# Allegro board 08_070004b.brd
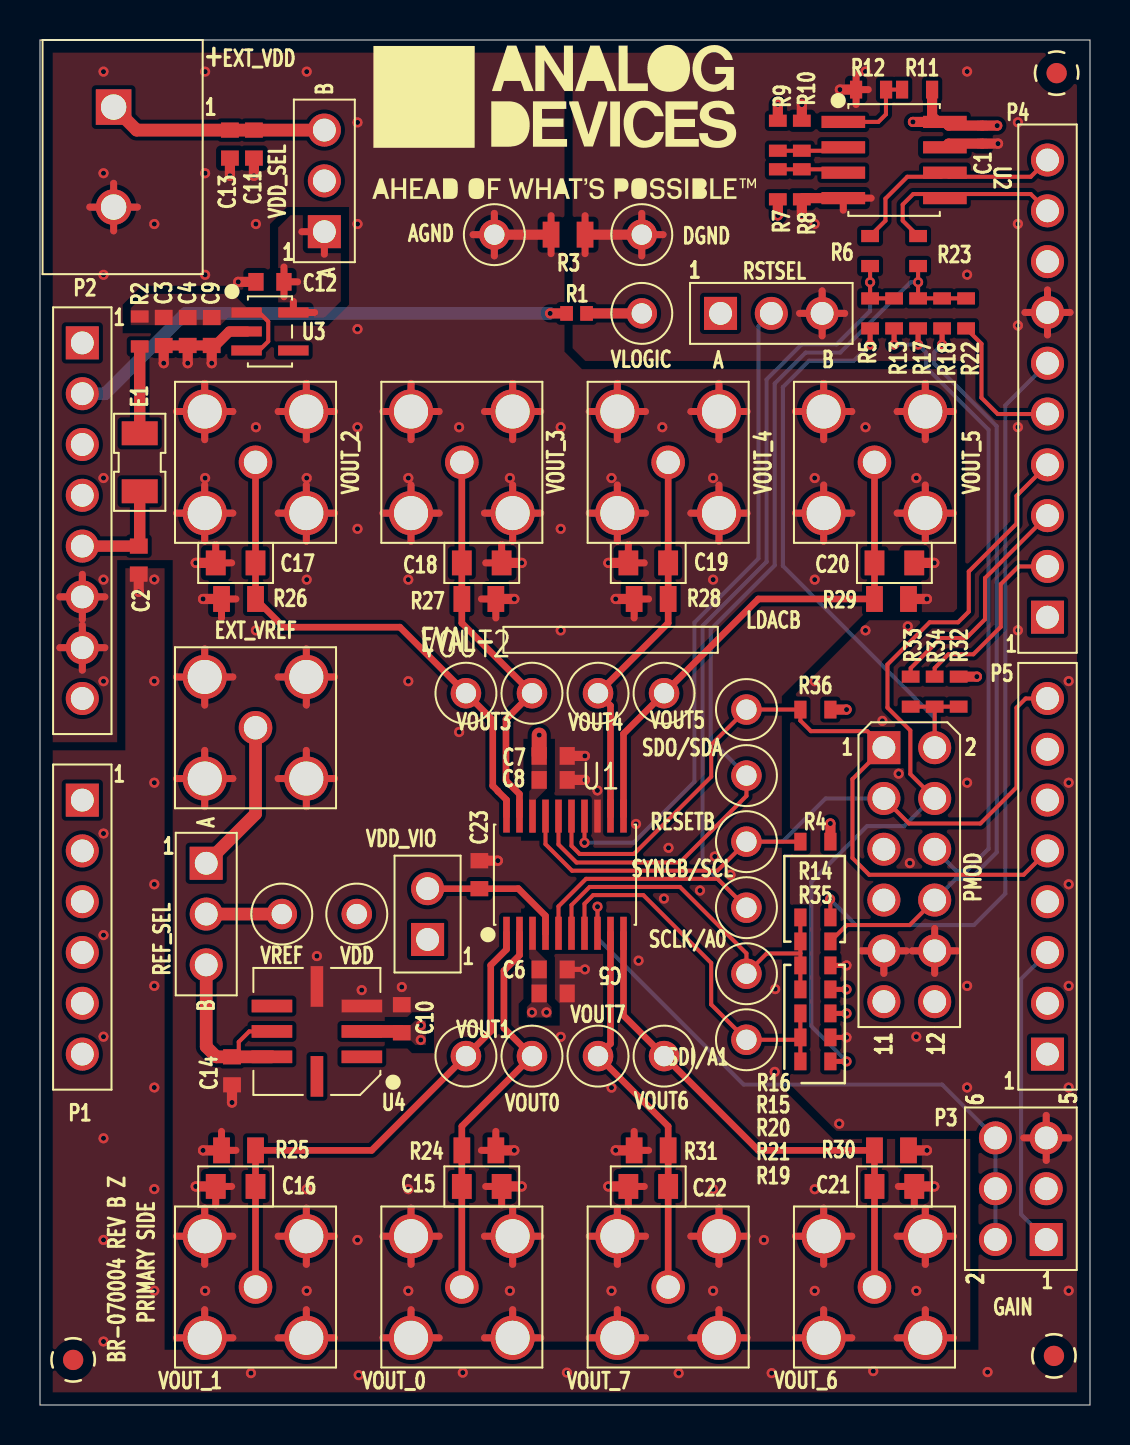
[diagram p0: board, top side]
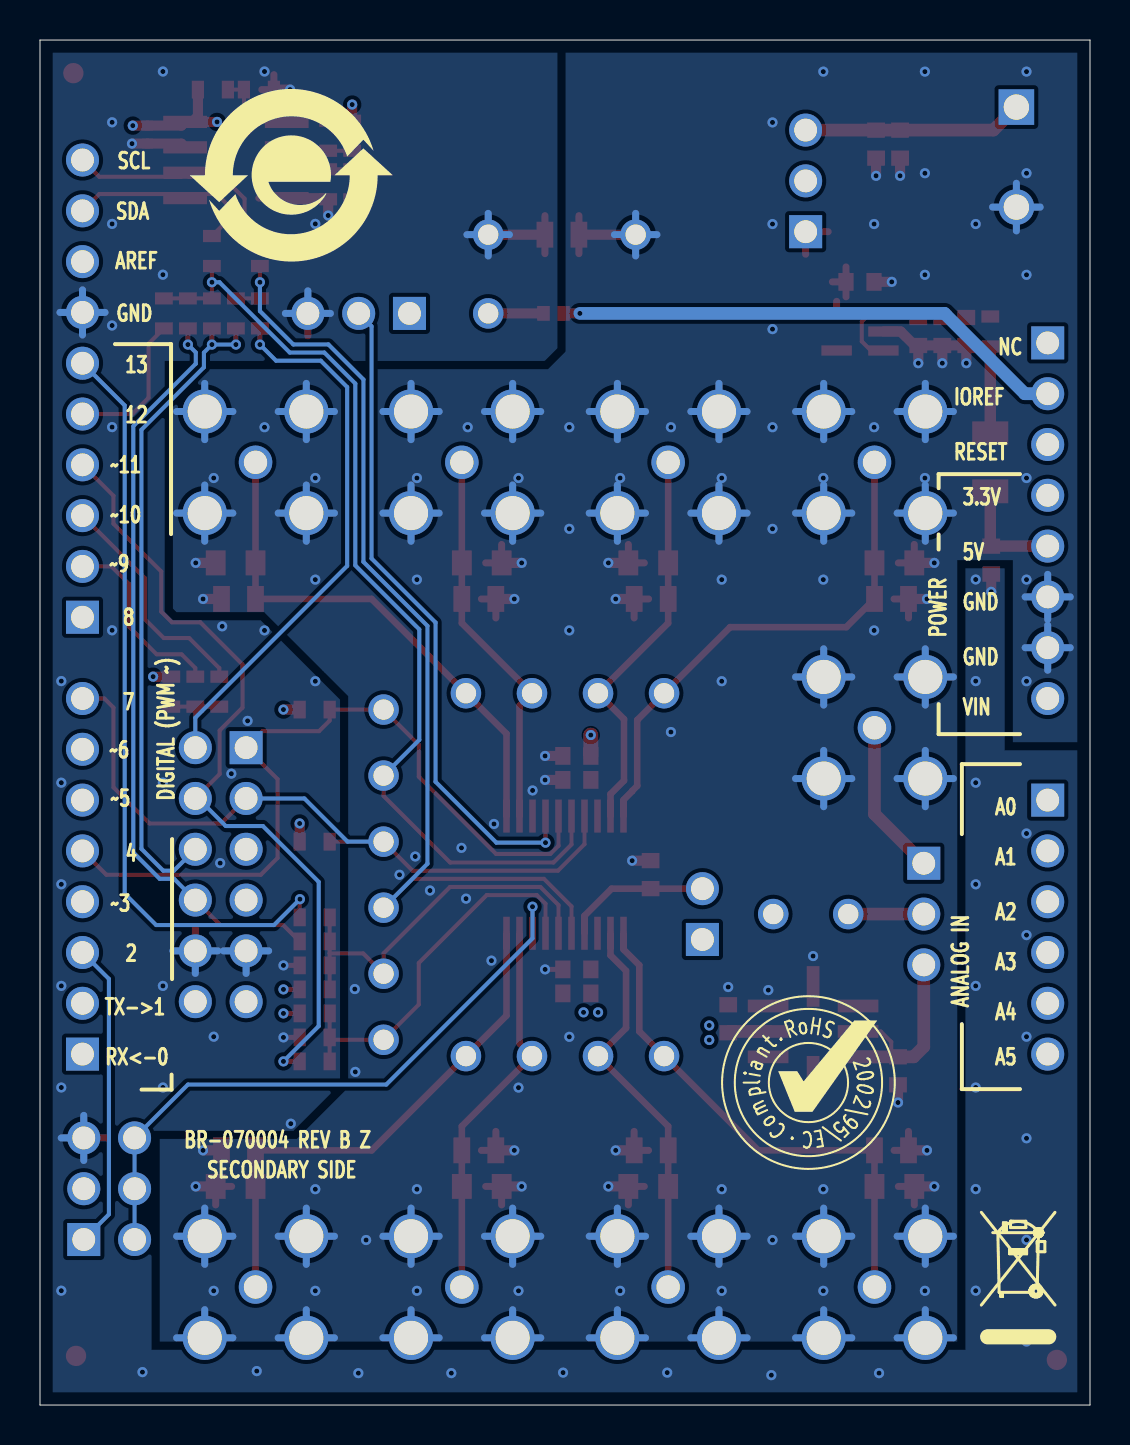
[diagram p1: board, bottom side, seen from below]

Outline 52.5 x 68.25 mm; copper layers: TOP, L2_GND, L3_PWR, BOTTOM. Coordinates in mm from the lower left corner of the outline.
Outline path: 0,68.25 52.5,68.25 52.5,0 0,0 0,68.25

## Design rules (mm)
constraint set DEFAULT: min track width 0.203
net group VOUT: nets DAC_OUT0 DAC_OUT1 DAC_OUT2 DAC_OUT3 DAC_OUT4 DAC_OUT5 DAC_OUT6 DAC_OUT7

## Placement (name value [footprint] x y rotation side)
AGND  BLK  [CNKEY5001TP]  22.72 58.52 90 top
C1  0.1uF  [C0402]  47.12 63.52 90 top
C2  10uF  [C0603]  4.94 42.25 270 top
C3  4.7UF  [C0603]  6.19 53.68 270 top
C4  0.1uF  [C0603]  7.39 53.68 270 top
C5  10uF  [C0603]  25.66 20.58 180 top
C6  0.1uF  [C0603]  25.66 21.78 0 top
C7  0.1uF  [C0603]  25.66 32.45 0 top
C8  0.1uF  [C0603]  25.66 31.25 0 top
C9  1uF  [C0603]  8.59 53.68 270 top
C10  0.1uF  [C0603]  18.09 19.31 90 top
C11  0.1uF  [C0603]  10.7 63.05 270 top
C12  1uF  [C0603]  11.5 56.16 180 top
C13  10uF  [C0603]  9.5 63.05 270 top
C14  1uF  [C0603]  9.6 16.71 270 top
C15  10NF  [C0805-2]  22.09 10.93 0 top
C16  10NF  [C0805-2]  9.78 10.93 180 top
C17  10NF  [C0805-2]  9.78 42.1 180 top
C18  10NF  [C0805-2]  22.09 42.1 0 top
C19  10NF  [C0805-2]  30.41 42.1 180 top
C20  10NF  [C0805-2]  42.72 42.1 0 top
C21  10NF  [C0805-2]  42.72 10.93 0 top
C22  10NF  [C0805-2]  30.41 10.93 180 top
C23  0.1uF  [C0603]  21.97 26.52 270 top
DGND  BLK  [CNKEY5001TP]  30.09 58.52 90 top
E1  600OHM  [L1206H71]  4.99 47.13 90 top
EXT_VDD  691102710002  [CNWURTH691102710002]  3.68 64.9 270 top
EXT_VREF  131-3701-261  [CNJOHNSON131-3701-261]  10.78 33.86 90 top
LDACB  WHT  [CNKEY5001TP]  35.32 34.77 0 top
NOREF  -  []  26.42 80.36 0 top
NOREF#2  -  []  96.35 33.6 0 top
NOREF#3  -  []  -60.3 -65 0 top
NOREF#4  -  [unnamed#2]  50.83 66.59 0 top
NOREF#5  -  []  0.46 344.29 0 top
NOREF#6  -  []  0 68.25 270 top
NOREF#7  -  [unnamed#2]  1.66 2.25 0 top
NOREF#8  -  []  48.67 371.65 0 top
NOREF#9  -  []  26.23 64.13 0 top
NOREF#10  -  []  52.5 0 90 top
NOREF#11  -  []  0 0 0 top
NOREF#12  -  []  52.5 0 90 top
NOREF#13  -  []  52.5 68.25 180 top
NOREF#14  -  []  0 68.25 0 top
NOREF#15  -  []  0 68.25 0 top
NOREF#16  -  []  0 0 0 top
NOREF#17  -  [unnamed#2]  50.7 2.45 0 top
NOREF#18  -  []  -49.91 -63.27 0 top
NOREF#19  -  []  2.12 17.55 0 top
NOREF#20  -  []  2.12 53.11 270 top
NOREF#21  -  []  0 0 0 top
NOREF#22  -  []  52.5 0 0 top
NOREF#23  -  []  2.12 17.55 0 top
NOREF#24  -  []  81.92 108.01 0 top
NOREF#25  -  []  39.94 61.49 180 bottom
NOREF#26  -  []  3.79 3.09 180 bottom
NOREF#27  -  []  14.08 16.12 180 bottom
P1  SSQ-106-03-G-S  [CNSAMTECSSQ-106-XX-X-S]  2.12 30.25 270 top
P2  SSQ-108-03-G-S  [CNSAMTECSSQ-108-XX-X-S]  2.12 53.11 270 top
P3  TSW-103-08-G-D  [CNSAMTEC2X3H330LD36]  50.31 8.27 90 top
P4  SSQ-110-03-G-S  [CNSAMTECSSQ-110-XX-X-S]  50.38 39.39 90 top
P5  SSQ-108-03-G-S  [CNSAMTECSSQ-108-XX-X-S]  50.38 17.55 90 top
PMOD  TSW-106-08-G-D  [CNBERG2X6H330LD36]  42.19 32.87 270 top
R1  0  [R0402]  26.83 54.58 0 top
R2  1.6  [R0603]  4.99 53.68 90 top
R3  0  [R0805]  26.4 58.52 180 top
R4  100K  [R0603]  38.77 28.17 180 top
R5  0  [R0603]  41.5 54.58 90 top
R6  0  [R0603]  41.5 57.7 270 top
R7  0  [R0603]  36.89 61.04 90 top
R8  100K  [R0603]  38.09 61.04 270 top
R9  100K  [R0603]  36.89 63.46 270 top
R10  0  [R0603]  38.09 63.46 90 top
R11  0  [R0603]  43.85 65.77 180 top
R12  100K  [R0603]  41.55 65.77 180 top
R13  0  [R0603]  42.7 54.58 90 top
R14  0  [R0603]  38.77 24.38 180 top
R15  0  [R0603]  38.77 20.78 180 top
R16  0  [R0603]  38.77 21.98 180 top
R17  0  [R0603]  43.9 54.58 90 top
R18  0  [R0603]  45.1 54.58 90 top
R19  0  [R0603]  38.77 17.18 180 top
R20  0  [R0603]  38.77 19.58 180 top
R21  0  [R0603]  38.77 18.38 180 top
R22  0  [R0603]  46.3 54.58 90 top
R23  0  [R0603]  43.9 57.7 270 top
R24  1K  [R0805]  21.94 12.73 0 top
R25  1K  [R0805]  9.93 12.73 180 top
R26  1K  [R0805]  9.93 40.3 180 top
R27  1K  [R0805]  21.94 40.3 0 top
R28  1K  [R0805]  30.56 40.3 180 top
R29  1K  [R0805]  42.57 40.3 0 top
R30  1K  [R0805]  42.57 12.73 0 top
R31  1K  [R0805]  30.56 12.73 180 top
R32  100K  [R0603]  45.93 35.67 90 top
R33  0  [R0603]  43.53 35.67 90 top
R34  0  [R0603]  44.73 35.67 90 top
R35  0  [R0603]  38.77 23.18 180 top
R36  100K  [R0603]  38.77 34.77 180 top
REF_SEL  YMC03SAAN  [CNTHMHDR1X3L300W100H343_A]  8.31 27.09 270 top
RESETB  WHT  [CNKEY5001TP]  35.32 28.17 0 top
RSTSEL  YMC03SAAN  [CNTHMHDR1X3L300W100H343_A]  34.03 54.58 0 top
SCLK/A0  WHT  [CNKEY5001TP]  35.32 21.56 0 top
SDI/A1  WHT  [CNKEY5001TP]  35.32 18.26 0 top
SDO/SDA  WHT  [CNKEY5001TP]  35.32 31.47 0 top
SYNCB/SCL  WHT  [CNKEY5001TP]  35.32 24.87 0 top
U1  AD5676RBRUZ  [TSSOP20]  26.25 26.52 0 top
U2  24AA32A-I/SN  [SO8]  42.7 62.25 270 top
U3  ADP121-AUJZ33  [TSOT-5]  11.5 53.68 270 top
U4  ADR4525DEZ  [LCC8]  13.85 18.68 90 top
VDD  RED  [CNKEY5001TP]  15.84 24.55 0 top
VDD_SEL  YMC03SAAN  [CNTHMHDR1X3L300W100H343_A]  14.22 58.67 90 top
VDD_VIO  M20-9990246  [CNHARWIN-M20-9990246]  19.38 23.28 90 top
VLOGIC  RED  [CNKEY5001TP]  30.09 54.58 0 top
VOUT0  RED  [CNKEY5001TP]  24.6 17.44 0 top
VOUT1  RED  [CNKEY5001TP]  21.3 17.44 0 top
VOUT2  RED  [CNKEY5001TP]  21.3 35.59 0 top
VOUT3  RED  [CNKEY5001TP]  24.6 35.59 0 top
VOUT4  RED  [CNKEY5001TP]  27.9 35.59 0 top
VOUT5  RED  [CNKEY5001TP]  31.2 35.59 0 top
VOUT6  RED  [CNKEY5001TP]  31.2 17.44 0 top
VOUT7  RED  [CNKEY5001TP]  27.9 17.44 0 top
VOUT_0  131-3701-261  [CNJOHNSON131-3701-261]  21.09 5.9 90 top
VOUT_1  131-3701-261  [CNJOHNSON131-3701-261]  10.78 5.9 90 top
VOUT_2  131-3701-261  [CNJOHNSON131-3701-261]  10.78 47.13 90 top
VOUT_3  131-3701-261  [CNJOHNSON131-3701-261]  21.09 47.13 90 top
VOUT_4  131-3701-261  [CNJOHNSON131-3701-261]  31.41 47.13 90 top
VOUT_5  131-3701-261  [CNJOHNSON131-3701-261]  41.72 47.13 90 top
VOUT_6  131-3701-261  [CNJOHNSON131-3701-261]  41.72 5.9 90 top
VOUT_7  131-3701-261  [CNJOHNSON131-3701-261]  31.41 5.9 90 top
VREF  RED  [CNKEY5001TP]  12.09 24.55 0 top

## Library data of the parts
AGND DGND = CNTP1P: Tolerance: N/A; User Part Number: UPN; alternate symbols: (CNKEY5001TP); part number: CNTP1P_TH-BLK,E005347,CNKEY5001TP; tolerance: N/A
C1 = CAP: User Part Number: UPN; Tolerance: 10; alternate symbols: (C0402L); part number: CAP_SM-0.1UF,16V,10,E028141,C0402; tolerance: 10
C2 = CAP: User Part Number: UPN; Tolerance: 20; alternate symbols: (C0603L); part number: CAP_SM-10UF,6.3V,20,E007143,C0603; tolerance: 20
C3 = CAP: User Part Number: UPN; Tolerance: 20; alternate symbols: (C0603L); part number: CAP_SM-4.7UF,10V,20,E054276,C0603; tolerance: 20
C4 C10 = CAP: User Part Number: UPN; Tolerance: 10; alternate symbols: (C0603L); part number: CAP_SM-0.1UF,50V,10,E031401,C0603; tolerance: 10
C5 C13 = CAP: User Part Number: UPN; Tolerance: 20; alternate symbols: (C0603L); part number: CAP_SM-10UF,10V,20,E022682,C0603; tolerance: 20
C6-C8 C11 C23 = CAP: User Part Number: UPN; Tolerance: 10; alternate symbols: (C0603L); part number: CAP_SM-0.1UF,16V,10,E015036,C0603; tolerance: 10
C9 C12 C14 = CAP: User Part Number: UPN; Tolerance: 10; alternate symbols: (C0603L); part number: CAP_SM-1UF,16V,10,E020111,C0603; tolerance: 10
C15-C22 = CAP: Tolerance: 10; User Part Number: UPN; alternate symbols: (C0805-2); part number: CAP_SM-10NF,200V,10,E042770,C0805-2; tolerance: 10
E1 = FERRITE: User Part Number: UPN; Tolerance: 25; alternate symbols: (L1206H71); part number: FERRITE_SM-600OHM,25,E048457,L1206H71; tolerance: 25
EXT_VDD = CN2P: Tolerance: N/A; User Part Number: UPN; alternate symbols: (CNWURTH691102710002); part number: CN2P_TH-691102710002,E048111,CNWURTH691102710002; tolerance: N/A
EXT_VREF VOUT_0-VOUT_7 = CNBNC5P: Tolerance: N/A; User Part Number: UPN; alternate symbols: (CNJOHNSON131-3701-261); part number: CNBNC5P_TH-131-3701-261,E012123,CNJOHNSON131-3701-261; tolerance: N/A
LDACB RESETB SCLK/A0 SDI/A1 SDO/SDA SYNCB/SCL = CNTP1P: Tolerance: N/A; User Part Number: UPN; alternate symbols: (CNKEY5001TP); part number: CNTP1P_TH-WHT,E006153,CNKEY5001TP; tolerance: N/A
P1 = CN6P: User Part Number: UPN; Tolerance: N/A; alternate symbols: (CNSAMTECSSQ-106-XX-X-S); part number: CN6P_TH-SSQ-106-03-G-S,E020477,CNSAMTECSSQ-106-XX-X-S; tolerance: N/A
P2 P5 = CN8P_A: User Part Number: UPN; Tolerance: N/A; alternate symbols: (CNSAMTECSSQ-108-XX-X-S); part number: CN8P_A_TH-SSQ-108-03-G-S,E020478,CNSAMTECSSQ-108-XX-X-S; tolerance: N/A
P3 = CN6P_ODD_EVEN: Tolerance: N/A; User Part Number: UPN; alternate symbols: (CNSAMTEC2X3H330LD36); part number: CN6P_ODD_EVEN_TH-TSW-103-08-G-D,E006383,CNSAMTEC2X3H330LD36; tolerance: N/A
P4 = CN10P: User Part Number: UPN; Tolerance: N/A; alternate symbols: (CNSAMTECSSQ-110-XX-X-S); part number: CN10P_TH-SSQ-110-03-G-S,E020479,CNSAMTECSSQ-110-XX-X-S; tolerance: N/A
PMOD = CN12P: Tolerance: N/A; User Part Number: UPN; alternate symbols: (CNBERG2X6H330LD36); part number: CN12P_TH-TSW-106-08-G-D,E000735,CNBERG2X6H330LD36; tolerance: N/A
R1 = RES: User Part Number: UPN; Tolerance: JUMPER; alternate symbols: (R0402); part number: RES_SM-0,E025232,1/16W,JUMPER,R0402; tolerance: JUMPER
R2 = RES: User Part Number: UPN; Tolerance: 1; alternate symbols: (R0603L); part number: RES_SM-1.6,E022192,1/5W,1,R0603; tolerance: 1
R3 = RES: User Part Number: UPN; Tolerance: JUMPER; alternate symbols: (R0805L); part number: RES_SM-0,E055446,1/2W,JUMPER,R0805; tolerance: JUMPER
R4 R36 = RES: User Part Number: UPN; Tolerance: 1; alternate symbols: (R0603L); part number: RES_SM-100K,E017869,1/10W,1,R0603; tolerance: 1
R5 R6 R13-R23 R33-R35 = RES: User Part Number: UPN; Tolerance: JUMPER; alternate symbols: (R0603L); part number: RES_SM-0,E034483,1/10W,JUMPER,R0603; tolerance: JUMPER
R7 R10 R11 = RES: User Part Number: UPN; Tolerance: JUMPER; alternate symbols: (R0603L); part number: RES_SM-0,E007502,1/10W,JUMPER,R0603; tolerance: JUMPER
R8 R9 R12 = RES: User Part Number: UPN; Tolerance: 1; alternate symbols: (R0603L); part number: RES_SM-100K,E018430,1/16W,1,R0603; tolerance: 1
R24-R31 = RES: User Part Number: UPN; Tolerance: 1; alternate symbols: (R0805L); part number: RES_SM-1K,E003415,1/8W,1,R0805; tolerance: 1
R32 = RES: User Part Number: UPN; Tolerance: 1; alternate symbols: (R0603L); part number: RES_SM-100K,E010279,1/10W,1,R0603; tolerance: 1
REF_SEL RSTSEL VDD_SEL = CN3P_JMPRSHRT: User Part Number: UPN; Tolerance: N/A; alternate symbols: (CNTHMHDR1X3L300W100H343_A); part number: CN3P_JMPRSHRT_TH-YMC03SAAN,E030075,CNTHMHDR1X3L300W100H343_A; tolerance: N/A
U1 = AD567XR: Tolerance: N/A; User Part Number: UPN; alternate symbols: (TSSOP20); part number: AD567XR_SM-AD5676RBRUZ,E026513,TSSOP20; tolerance: N/A
U2 = IC24XX32A_V2: Tolerance: N/A; User Part Number: UPN; alternate symbols: (SO8); part number: IC24XX32A_V2_SM-24AA32A-I/SN,E034913,SO8; tolerance: N/A
U3 = ADP121: User Part Number: UPN; Tolerance: N/A; alternate symbols: (TSOT-5); part number: ADP121_SM-ADP121-AUJZ33,E013943,TSOT-5; tolerance: N/A
U4 = ADR45XX_V2: User Part Number: UPN; Tolerance: N/A; alternate symbols: (LCC8); part number: ADR45XX_V2_SM-ADR4525DEZ,E055648,LCC8; tolerance: N/A
VDD VLOGIC VOUT0-VOUT7 VREF = CNTP1P: Tolerance: N/A; User Part Number: UPN; alternate symbols: (CNKEY5001TP); part number: CNTP1P_TH-RED,E016323,CNKEY5001TP; tolerance: N/A
VDD_VIO = CN2P: Tolerance: N/A; User Part Number: UPN; alternate symbols: (CNHARWIN-M20-9990246); part number: CN2P_TH-M20-9990246,E010843,CNHARWIN-M20-9990246; tolerance: N/A

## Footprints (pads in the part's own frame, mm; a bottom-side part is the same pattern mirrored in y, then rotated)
C0402
  rect 0.483x0.559 smd: 1(-0.45,0) 2(0.45,0)
C0603
  rect 0.762x0.889 smd: 1(-0.7,0) 2(0.7,0)
C0805-2
  rect 0.991x1.245 smd: 1(-0.995,0) 2(0.995,0)
CNBERG2X6H330LD36
  rect 1.651x1.651 hole 1.143: 1(0,0)
  round 1.651 hole 1.143: 2(0,2.54) 3(2.54,0) 4(2.54,2.54) 5(5.08,0) 6(5.08,2.54) 7(7.62,0) 8(7.62,2.54) 9(10.16,0) 10(10.16,2.54) 11(12.7,0) 12(12.7,2.54)
CNHARWIN-M20-9990246
  rect 1.651x1.651 hole 1.143: 1(0,0)
  round 1.651 hole 1.143: 2(2.54,0)
CNJOHNSON131-3701-261
  round 1.676 hole 1.168: 1(0,0)
  round 2.21 hole 1.702: 2(-2.54,2.54) 3(2.54,2.54) 4(2.54,-2.54) 5(-2.54,-2.54)
CNKEY5001TP
  round 1.524 hole 1.016: 1(0,0)
CNSAMTEC2X3H330LD36
  rect 1.651x1.651 hole 1.143: 1(0,0)
  round 1.651 hole 1.143: 2(0,2.54) 3(2.54,0) 4(2.54,2.54) 5(5.08,0) 6(5.08,2.54)
CNSAMTECSSQ-106-XX-X-S
  rect 1.651x1.651 hole 1.143: 1(0,0)
  round 1.651 hole 1.143: 2(2.54,0) 3(5.08,0) 4(7.62,0) 5(10.16,0) 6(12.7,0)
CNSAMTECSSQ-108-XX-X-S
  rect 1.651x1.651 hole 1.143: 1(0,0)
  round 1.651 hole 1.143: 2(2.54,0) 3(5.08,0) 4(7.62,0) 5(10.16,0) 6(12.7,0) 7(15.24,0) 8(17.78,0)
CNSAMTECSSQ-110-XX-X-S
  rect 1.651x1.651 hole 1.143: 1(0,0)
  round 1.651 hole 1.143: 2(2.54,0) 3(5.08,0) 4(7.62,0) 5(10.16,0) 6(12.7,0) 7(15.24,0) 8(17.78,0) 9(20.32,0) 10(22.86,0)
CNTHMHDR1X3L300W100H343_A
  rect 1.651x1.651 hole 1.143: 1(0,0)
  round 1.651 hole 1.143: 2(2.54,0) 3(5.08,0)
CNWURTH691102710002
  rect 1.778x1.778 hole 1.27: 1(0,0)
  round 1.778 hole 1.27: 2(5,0)
L1206H71
  rect 1.194x1.803 smd: 1(-1.45,0) 2(1.45,0)
LCC8
  rect 0.635x2.032 smd: 1(-1.27,-2.248) 2(0,-2.248) 3(1.27,-2.248) 5(1.27,2.248) 6(0,2.248) 7(-1.27,2.248)
  rect 2.032x0.635 smd: 4(2.248,0) 8(-2.248,0)
R0402
  rect 0.635x0.737 smd: 1(-0.5,0) 2(0.5,0)
R0603
  rect 0.61x0.889 smd: 1(-0.75,0) 2(0.75,0)
R0805
  rect 0.838x1.295 smd: 1(-0.85,0) 2(0.85,0)
SO8
  rect 0.61x2.184 smd: 1(-1.905,-2.54) 2(-0.635,-2.54) 3(0.635,-2.54) 4(1.905,-2.54) 5(1.905,2.54) 6(0.635,2.54) 7(-0.635,2.54) 8(-1.905,2.54)
TSOT-5
  rect 0.508x1.524 smd: 1(-0.95,-1.17) 2(0,-1.17) 3(0.95,-1.17) 4(0.95,1.17) 5(-0.95,1.17)
TSSOP20
  rect 0.33x1.651 smd: 1(-2.925,-2.93) 2(-2.275,-2.93) 3(-1.625,-2.93) 4(-0.975,-2.93) 5(-0.325,-2.93) 6(0.325,-2.93) 7(0.975,-2.93) 8(1.625,-2.93) 9(2.275,-2.93) 10(2.925,-2.93) 11(2.925,2.93) 12(2.275,2.93) 13(1.625,2.93) 14(0.975,2.93) 15(0.325,2.93) 16(-0.325,2.93) 17(-0.975,2.93) 18(-1.625,2.93) 19(-2.275,2.93) 20(-2.925,2.93)
unnamed#2
  round 1.016 smd: (0,0)

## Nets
+5V_SUP: C3.1 C4.1 C9.1 R2.2(N2) U3.1 U3.3
AGND: AGND.1(N1) C3.2(N2) C4.2(N2) C5.1 C6.2(N2) C7.2(N2) C8.2(N2) C9.2(N2) C10.2(N2) C11.2(N2) C12.2(N2) C13.2(N2) C14.2(N2) C15.2(N2) C16.2(N2) C17.2(N2) C18.2(N2) C19.2(N2) C20.2(N2) C21.2(N2) C22.2(N2) C23.1 EXT_VDD.2(N2) EXT_VREF.2 EXT_VREF.3 EXT_VREF.4 EXT_VREF.5(SH4) P2.6 P2.7 R3.2(N2) R24.2(N2) R25.2(N2) R26.2(N2) R27.2(N2) R28.2(N2) R29.2(N2) R30.2(N2) R31.2(N2) U1.13 U3.2 U4.3 U4.4 VOUT_0.2 VOUT_0.3 VOUT_0.4 VOUT_0.5(SH4) VOUT_1.2 VOUT_1.3 VOUT_1.4 VOUT_1.5(SH4) VOUT_2.2 VOUT_2.3 VOUT_2.4 VOUT_2.5(SH4) VOUT_3.2 VOUT_3.3 VOUT_3.4 VOUT_3.5(SH4) VOUT_4.2 VOUT_4.3 VOUT_4.4 VOUT_4.5(SH4) VOUT_5.2 VOUT_5.3 VOUT_5.4 VOUT_5.5(SH4) VOUT_6.2 VOUT_6.3 VOUT_6.4 VOUT_6.5(SH4) VOUT_7.2 VOUT_7.3 VOUT_7.4 VOUT_7.5(SH4)
DGND: C1.1 C2.2(N2) DGND.1(N1) P3.5 P4.7 PMOD.9(N9) PMOD.10 R3.1 R8.2(N2) R10.2(N2) R12.2(N2) R16.1 R21.1 RSTSEL.3(S3) U2.4 U2.7(WP)
VDD_EXT: C11.1 C13.1 EXT_VDD.1 VDD_SEL.3(S3)
ARD_SCL: P4.10 R6.1 U2.6
ARD_SCLK: P4.6 R14.1
ARD_SDA: P4.9(N9) R23.1 U2.5
ARD_SDI: P4.4 PMOD.4 R19.1
ARD_SDO: P4.5 R22.1
ARD_SYNCB: PMOD.2 R5.1 R32.1 R33.1 R34.1
DAC_GAIN: P3.2 P3.4 P3.6(N6) U1.8
DAC_LDACB: LDACB.1(N1) P5.5 PMOD.1 R36.2(N2) U1.15
DAC_OUT0: C15.1 R24.1 U1.2 VOUT0.1(N1) VOUT_0.1
DAC_OUT1: C16.1 R25.1 U1.1 VOUT1.1(N1) VOUT_1.1
DAC_OUT2: C17.1 R26.1 U1.20 VOUT2.1(N1) VOUT_2.1
DAC_OUT3: C18.1 R27.1 U1.19 VOUT3.1(N1) VOUT_3.1
DAC_OUT4: C19.1 R28.1 U1.12 VOUT4.1(N1) VOUT_4.1
DAC_OUT5: C20.1 R29.1 U1.11 VOUT5.1(N1) VOUT_5.1
DAC_OUT6: C21.1 R30.1 U1.10 VOUT6.1(N1) VOUT_6.1
DAC_OUT7: C22.1 R31.1 U1.9 VOUT7.1(N1) VOUT_7.1
DAC_RESETB: P5.8(N8) PMOD.3 R4.2(N2) RESETB.1(N1) U1.17
DAC_RSTSEL: RSTSEL.2 U1.14
DAC_SCLK/A0: R14.2(N2) R15.2(N2) R16.2(N2) R35.2(N2) SCLK/A0.1(N1) U1.6
DAC_SDI/A1: R19.2(N2) R20.2(N2) R21.2(N2) SDI/A1.1(N1) U1.7
DAC_SDO/SDA: R17.2(N2) R18.2(N2) R22.2(N2) R23.2(N2) SDO/SDA.1(N1) U1.16
DAC_SYNCB/SCL: R5.2(N2) R6.2(N2) R13.2(N2) SYNCB/SCL.1(N1) U1.5
DAC_VDD: C5.2(N2) C6.1 C10.1 U1.3 U4.2 VDD.1(N1) VDD_SEL.2 VDD_VIO.1
DAC_VLOGIC: C1.2(N2) C23.2(N2) P3.3 PMOD.11 PMOD.12 R1.2(N2) R4.1 R7.1 R9.1 R11.1 R15.1 R20.1 R32.2(N2) R36.1 RSTSEL.1 U1.4 U2.8 VDD_VIO.2(N2) VLOGIC.1(N1)
DAC_VREF: C7.1 C8.1 REF_SEL.2 U1.18(VREFOUT) VREF.1(N1)
GAIN_IO: P3.1 P5.3
LDO_3V3: C12.1 U3.5(VOUT) VDD_SEL.1
PMOD_SCLK/SDA: PMOD.8 R18.1 R35.1
PMOD_SDO/SCL: PMOD.6 R13.1 R17.1
UNNAMED_3_CAP_I60_N1: C2.1 E1.1 P2.5
UNNAMED_3_CN8PA_I4_N2: P2.2 R1.1
UNNAMED_3_CN10P_I1_N2: P4.2 R34.2(N2)
UNNAMED_3_CN10P_I1_N3: P4.3 R33.2(N2)
UNNAMED_3_FERRITE_I66_N2: E1.2(N2) R2.1
UNNAMED_3_IC24XX32AV2_I22_A1: R9.2(N2) R10.1 U2.2
UNNAMED_3_IC24XX32AV2_I22_A2: R7.2(N2) R8.1 U2.3
UNNAMED_3_RES_I15_N1: R11.2(N2) R12.1 U2.1
VREF_2V5: C14.1 REF_SEL.3(S3) U4.6(VOUTSENSE) U4.7
VREF_EXT: EXT_VREF.1 REF_SEL.1

Pads without a net: P1 1 2 3 4 5 6; P2 1 3 4 8; P4 1 8; P5 1 2 4 6 7; PMOD 5 7; U3 4; U4 1 5 8

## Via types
v1: diameter 0.508, hole 0.254, TOP to BOTTOM, 175 vias

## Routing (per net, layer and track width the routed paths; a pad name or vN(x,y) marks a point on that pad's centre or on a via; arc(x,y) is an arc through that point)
+5V_SUP: length 3.5
  TOP w0.203: U3.3 10.96,52.73 11.41,53.18 11.41,54.17 10.96,54.63 U3.1
AGND: length 683.1
  TOP w0.254: C6.2 v1(27.24,21.78)
  TOP w0.35: VOUT_3.4 25.04,49.67 ; VOUT_3.4 23.63,48.27 ; VOUT_3.4 22.23,49.67 ; VOUT_3.4 23.63,51.08 ; EXT_VDD.2 4.87,59.9 ; EXT_VDD.2 3.68,61.09 ; EXT_VDD.2 2.49,59.9 ; EXT_VDD.2 3.68,58.71 ; 25.55,57.57 R3.2 25.55,59.47 ; 27.46,49.67 VOUT_4.3 ; VOUT_4.3 28.87,48.27 ; VOUT_4.3 28.87,51.08 ; VOUT_4.3 30.27,49.67 ; VOUT_7.4 33.95,9.85 ; VOUT_7.4 33.95,7.03 ; VOUT_7.4 35.35,8.44 ; VOUT_7.4 32.54,8.44 ; 8.24,48.27 VOUT_2.3 ; VOUT_2.3 9.64,49.67 ; VOUT_2.3 8.24,51.08 ; VOUT_2.3 6.83,49.67 ; 21.65,58.52 AGND.1 ; AGND.1 22.72,57.45 ; AGND.1 22.72,59.58 ; VOUT_0.3 18.55,9.85 ; VOUT_0.3 17.15,8.44 ; VOUT_0.3 18.55,7.03 ; VOUT_0.3 19.96,8.44 ; 23.63,7.03 VOUT_0.4 ; VOUT_0.4 22.23,8.44 ; VOUT_0.4 25.04,8.44 ; VOUT_0.4 23.63,9.85 ; P2.7 2.12,38.99 ; P2.7 2.12,36.74 ; P2.7 3.24,37.87 ; P2.7 0.99,37.87 ; 2.12,39.28 P2.6 ; P2.6 2.12,41.53 ; P2.6 3.24,40.41 ; P2.6 0.99,40.41 ; 9.08,39.35 R26.2 9.8,40.3 ; 22.79,39.35 R27.2 22.07,40.3 ; 30.43,12.73 R31.2 29.71,13.68 ; VOUT_6.5 44.26,4.77 ; VOUT_6.5 42.86,3.36 ; VOUT_6.5 45.67,3.36 ; VOUT_5.3 40.59,49.67 ; VOUT_5.3 39.18,51.08 ; VOUT_5.3 39.18,48.27 ; VOUT_5.3 37.78,49.67 ; 9.58,42.1 C17.2 8.79,43.03 ; 23.08,43.03 C18.2 22.29,42.1 ; 32.54,3.36 VOUT_7.5 ; VOUT_7.5 35.35,3.36 ; VOUT_7.5 33.95,4.77 ; 23.08,10 C15.2 22.29,10.93 ; 11.91,44.59 VOUT_2.5 ; VOUT_2.5 14.72,44.59 ; VOUT_2.5 13.32,43.19 ; VOUT_2.5 13.32,46 ; 42.92,10.93 C21.2 43.71,10 ; VOUT_6.2 39.18,4.77 ; VOUT_6.2 37.78,3.36 ; VOUT_6.2 40.59,3.36 ; VOUT_4.5 33.95,46 ; VOUT_4.5 33.95,43.19 ; VOUT_4.5 32.54,44.59 ; VOUT_4.5 35.35,44.59 ; 37.78,8.44 VOUT_6.3 ; VOUT_6.3 40.59,8.44 ; VOUT_6.3 39.18,9.85 ; VOUT_6.3 39.18,7.03 ; 17.15,49.67 VOUT_3.3 ; VOUT_3.3 19.96,49.67 ; VOUT_3.3 18.55,51.08 ; VOUT_3.3 18.55,48.27 ; 9.8,12.73 R25.2 9.08,13.68 ; 11.91,49.67 VOUT_2.4 ; VOUT_2.4 13.32,51.08 ; VOUT_2.4 14.72,49.67 ; VOUT_2.4 13.32,48.27 ; VOUT_3.5 23.63,46 ; VOUT_3.5 23.63,43.19 ; VOUT_3.5 22.23,44.59 ; VOUT_3.5 25.04,44.59 ; EXT_VREF.5 13.32,32.73 ; EXT_VREF.5 11.91,31.32 ; EXT_VREF.5 14.72,31.32 ; EXT_VREF.5 13.32,29.92 ; 22.79,13.68 R24.2 22.07,12.73 ; EXT_VREF.2 8.24,32.73 ; EXT_VREF.2 6.83,31.32 ; EXT_VREF.2 9.64,31.32 ; EXT_VREF.2 8.24,29.92 ; VOUT_3.2 18.55,46 ; VOUT_3.2 19.96,44.59 ; VOUT_3.2 18.55,43.19 ; VOUT_3.2 17.15,44.59 ; 29.42,10 C22.2 30.21,10.93 ; 27.46,44.59 VOUT_4.2 ; VOUT_4.2 30.27,44.59 ; VOUT_4.2 28.87,46 ; VOUT_4.2 28.87,43.19 ; VOUT_1.4 13.32,9.85 ; VOUT_1.4 11.91,8.44 ; VOUT_1.4 14.72,8.44 ; VOUT_1.4 13.32,7.03 ; VOUT_2.2 8.24,46 ; VOUT_2.2 6.83,44.59 ; VOUT_2.2 8.24,43.19 ; VOUT_2.2 9.64,44.59 ; VOUT_4.4 35.35,49.67 ; VOUT_4.4 33.95,51.08 ; VOUT_4.4 32.54,49.67 ; VOUT_4.4 33.95,48.27 ; EXT_VREF.4 13.32,37.81 ; EXT_VREF.4 13.32,35 ; EXT_VREF.4 11.91,36.4 ; EXT_VREF.4 14.72,36.4 ; VOUT_0.5 23.63,4.77 ; VOUT_0.5 22.23,3.36 ; VOUT_0.5 25.04,3.36 ; VOUT_1.5 14.72,3.36 ; VOUT_1.5 13.32,4.77 ; VOUT_1.5 11.91,3.36 ; 42.86,44.59 VOUT_5.5 ; VOUT_5.5 44.26,46 ; VOUT_5.5 44.26,43.19 ; VOUT_5.5 45.67,44.59 ; VOUT_0.2 19.96,3.36 ; VOUT_0.2 17.15,3.36 ; VOUT_0.2 18.55,4.77 ; VOUT_5.4 44.26,51.08 ; VOUT_5.4 42.86,49.67 ; VOUT_5.4 45.67,49.67 ; VOUT_5.4 44.26,48.27 ; 39.18,43.19 VOUT_5.2 ; VOUT_5.2 37.78,44.59 ; VOUT_5.2 40.59,44.59 ; VOUT_5.2 39.18,46 ; 30.43,40.3 R28.2 29.71,39.35 ; EXT_VREF.3 8.24,37.81 ; EXT_VREF.3 8.24,35 ; EXT_VREF.3 9.64,36.4 ; EXT_VREF.3 6.83,36.4 ; 27.46,3.36 VOUT_7.2 ; VOUT_7.2 30.27,3.36 ; VOUT_7.2 28.87,4.77 ; 6.83,3.36 VOUT_1.2 ; VOUT_1.2 9.64,3.36 ; VOUT_1.2 8.24,4.77 ; 44.26,7.03 VOUT_6.4 ; VOUT_6.4 42.86,8.44 ; VOUT_6.4 44.26,9.85 ; VOUT_6.4 45.67,8.44 ; VOUT_7.3 28.87,9.85 ; VOUT_7.3 30.27,8.44 ; VOUT_7.3 28.87,7.03 ; VOUT_7.3 27.46,8.44 ; 6.83,8.44 VOUT_1.3 ; VOUT_1.3 8.24,9.85 ; VOUT_1.3 9.64,8.44 ; VOUT_1.3 8.24,7.03 ; 29.42,43.03 C19.2 30.21,42.1 ; 9.58,10.93 C16.2 8.79,10
  TOP w0.508: C4.2 v1(7.39,52.09) ; C4.2 C3.2 v1(6.19,52.09) ; C4.2 C9.2 ; R24.2 v1(23.72,12.73) ; C22.2 v1(28.42,10.93) ; C18.2 v1(24.08,42.1) ; R25.2 v1(8.15,12.73) ; C11.2 v1(10.7,61.46) ; U3.2 9.47,53.68 8.77,52.98 C9.2 ; C16.2 v1(7.79,10.93) ; R30.2 v1(44.35,12.73) ; C15.2 v1(24.08,10.93) ; R26.2 v1(8.15,40.3) ; C21.2 v1(44.71,10.93) ; C9.2 v1(8.59,52.09) ; C14.2 v1(9.6,15.12) ; C12.2 v1(9.91,56.16) ; R29.2 v1(44.35,40.3) ; C20.2 v1(44.71,42.1) ; C13.2 v1(9.5,61.46) ; R31.2 v1(28.78,12.73) ; C19.2 v1(28.42,42.1) ; C17.2 v1(7.79,42.1) ; R3.2 AGND.1 ; v1(22.89,27.22) C23.1 ; R27.2 v1(23.72,40.3) ; C7.2 v1(27.24,32.45) ; R28.2 v1(28.78,40.3) ; C8.2 v1(27.24,31.25)
  L2_GND w0.35: 22.23,3.36 VOUT_0.5 ; VOUT_0.5 25.04,3.36 ; VOUT_0.5 23.63,4.77 ; 11.91,3.36 VOUT_1.5 ; VOUT_1.5 13.32,4.77 ; VOUT_1.5 14.72,3.36 ; 8.24,7.03 VOUT_1.3 ; VOUT_1.3 9.64,8.44 ; VOUT_1.3 8.24,9.85 ; VOUT_1.3 6.83,8.44 ; VOUT_7.3 28.87,9.85 ; VOUT_7.3 27.46,8.44 ; VOUT_7.3 30.27,8.44 ; VOUT_7.3 28.87,7.03 ; P2.6 3.24,40.41 ; P2.6 2.12,39.28 ; P2.6 0.99,40.41 ; P2.6 2.12,41.53 ; 37.78,3.36 VOUT_6.2 ; VOUT_6.2 40.59,3.36 ; VOUT_6.2 39.18,4.77 ; 23.63,7.03 VOUT_0.4 ; VOUT_0.4 22.23,8.44 ; VOUT_0.4 25.04,8.44 ; VOUT_0.4 23.63,9.85 ; VOUT_6.3 40.59,8.44 ; VOUT_6.3 39.18,9.85 ; VOUT_6.3 39.18,7.03 ; VOUT_6.3 37.78,8.44 ; VOUT_5.2 40.59,44.59 ; VOUT_5.2 39.18,46 ; VOUT_5.2 39.18,43.19 ; VOUT_5.2 37.78,44.59 ; VOUT_4.2 30.27,44.59 ; VOUT_4.2 28.87,43.19 ; VOUT_4.2 28.87,46 ; VOUT_4.2 27.46,44.59 ; 33.95,7.03 VOUT_7.4 ; VOUT_7.4 33.95,9.85 ; VOUT_7.4 32.54,8.44 ; VOUT_7.4 35.35,8.44 ; VOUT_5.4 45.67,49.67 ; VOUT_5.4 44.26,51.08 ; VOUT_5.4 42.86,49.67 ; VOUT_5.4 44.26,48.27 ; VOUT_6.4 44.26,9.85 ; VOUT_6.4 45.67,8.44 ; VOUT_6.4 42.86,8.44 ; VOUT_6.4 44.26,7.03 ; AGND.1 23.78,58.52 ; AGND.1 22.72,57.45 ; AGND.1 22.72,59.58 ; AGND.1 21.65,58.52 ; VOUT_0.2 19.96,3.36 ; VOUT_0.2 18.55,4.77 ; VOUT_0.2 17.15,3.36 ; VOUT_4.5 35.35,44.59 ; VOUT_4.5 33.95,46 ; VOUT_4.5 32.54,44.59 ; VOUT_4.5 33.95,43.19 ; VOUT_3.5 25.04,44.59 ; VOUT_3.5 23.63,46 ; VOUT_3.5 22.23,44.59 ; VOUT_3.5 23.63,43.19 ; 8.24,48.27 VOUT_2.3 ; VOUT_2.3 6.83,49.67 ; VOUT_2.3 9.64,49.67 ; VOUT_2.3 8.24,51.08 ; VOUT_6.5 44.26,4.77 ; VOUT_6.5 45.67,3.36 ; VOUT_6.5 42.86,3.36 ; 32.54,49.67 VOUT_4.4 ; VOUT_4.4 35.35,49.67 ; VOUT_4.4 33.95,48.27 ; VOUT_4.4 33.95,51.08 ; 13.32,48.27 VOUT_2.4 ; VOUT_2.4 14.72,49.67 ; VOUT_2.4 11.91,49.67 ; VOUT_2.4 13.32,51.08 ; VOUT_1.4 13.32,9.85 ; VOUT_1.4 14.72,8.44 ; VOUT_1.4 11.91,8.44 ; VOUT_1.4 13.32,7.03 ; VOUT_5.5 45.67,44.59 ; VOUT_5.5 42.86,44.59 ; VOUT_5.5 44.26,43.19 ; VOUT_5.5 44.26,46 ; 27.46,49.67 VOUT_4.3 ; VOUT_4.3 30.27,49.67 ; VOUT_4.3 28.87,48.27 ; VOUT_4.3 28.87,51.08 ; 18.55,7.03 VOUT_0.3 ; VOUT_0.3 18.55,9.85 ; VOUT_0.3 19.96,8.44 ; VOUT_0.3 17.15,8.44 ; EXT_VREF.4 14.72,36.4 ; EXT_VREF.4 11.91,36.4 ; EXT_VREF.4 13.32,37.81 ; EXT_VREF.4 13.32,35 ; VOUT_3.3 18.55,51.08 ; VOUT_3.3 19.96,49.67 ; VOUT_3.3 17.15,49.67 ; VOUT_3.3 18.55,48.27 ; 22.23,49.67 VOUT_3.4 ; VOUT_3.4 23.63,48.27 ; VOUT_3.4 23.63,51.08 ; VOUT_3.4 25.04,49.67 ; 6.83,3.36 VOUT_1.2 ; VOUT_1.2 8.24,4.77 ; VOUT_1.2 9.64,3.36 ; 2.49,59.9 EXT_VDD.2 ; EXT_VDD.2 3.68,61.09 ; EXT_VDD.2 4.87,59.9 ; EXT_VDD.2 3.68,58.71 ; EXT_VREF.5 14.72,31.32 ; EXT_VREF.5 13.32,29.92 ; EXT_VREF.5 11.91,31.32 ; EXT_VREF.5 13.32,32.73 ; VOUT_2.5 14.72,44.59 ; VOUT_2.5 11.91,44.59 ; VOUT_2.5 13.32,43.19 ; VOUT_2.5 13.32,46 ; 39.18,48.27 VOUT_5.3 ; VOUT_5.3 37.78,49.67 ; VOUT_5.3 39.18,51.08 ; VOUT_5.3 40.59,49.67 ; VOUT_7.2 30.27,3.36 ; VOUT_7.2 28.87,4.77 ; VOUT_7.2 27.46,3.36 ; 2.12,36.74 P2.7 ; P2.7 2.12,38.99 ; P2.7 0.99,37.87 ; P2.7 3.24,37.87 ; EXT_VREF.2 9.64,31.32 ; EXT_VREF.2 8.24,29.92 ; EXT_VREF.2 8.24,32.73 ; EXT_VREF.2 6.83,31.32 ; 18.55,43.19 VOUT_3.2 ; VOUT_3.2 17.15,44.59 ; VOUT_3.2 19.96,44.59 ; VOUT_3.2 18.55,46 ; EXT_VREF.3 8.24,37.81 ; EXT_VREF.3 6.83,36.4 ; EXT_VREF.3 9.64,36.4 ; EXT_VREF.3 8.24,35 ; 8.24,43.19 VOUT_2.2 ; VOUT_2.2 8.24,46 ; VOUT_2.2 9.64,44.59 ; VOUT_2.2 6.83,44.59 ; 32.54,3.36 VOUT_7.5 ; VOUT_7.5 35.35,3.36 ; VOUT_7.5 33.95,4.77
  BOTTOM w0.35: 39.18,7.03 VOUT_6.3 ; VOUT_6.3 40.59,8.44 ; VOUT_6.3 39.18,9.85 ; VOUT_6.3 37.78,8.44 ; VOUT_1.3 9.64,8.44 ; VOUT_1.3 8.24,9.85 ; VOUT_1.3 6.83,8.44 ; VOUT_1.3 8.24,7.03 ; 11.91,49.67 VOUT_2.4 ; VOUT_2.4 14.72,49.67 ; VOUT_2.4 13.32,51.08 ; VOUT_2.4 13.32,48.27 ; 0.99,37.87 P2.7 ; P2.7 2.12,36.74 ; P2.7 2.12,38.99 ; P2.7 3.24,37.87 ; 17.15,44.59 VOUT_3.2 ; VOUT_3.2 18.55,46 ; VOUT_3.2 18.55,43.19 ; VOUT_3.2 19.96,44.59 ; VOUT_2.3 9.64,49.67 ; VOUT_2.3 8.24,51.08 ; VOUT_2.3 6.83,49.67 ; VOUT_2.3 8.24,48.27 ; 23.63,48.27 VOUT_3.4 ; VOUT_3.4 22.23,49.67 ; VOUT_3.4 25.04,49.67 ; VOUT_3.4 23.63,51.08 ; 0.99,40.41 P2.6 ; P2.6 2.12,41.53 ; P2.6 2.12,39.28 ; P2.6 3.24,40.41 ; VOUT_7.2 28.87,4.77 ; VOUT_7.2 30.27,3.36 ; VOUT_7.2 27.46,3.36 ; 11.91,3.36 VOUT_1.5 ; VOUT_1.5 14.72,3.36 ; VOUT_1.5 13.32,4.77 ; VOUT_0.4 25.04,8.44 ; VOUT_0.4 23.63,7.03 ; VOUT_0.4 23.63,9.85 ; VOUT_0.4 22.23,8.44 ; 11.91,8.44 VOUT_1.4 ; VOUT_1.4 14.72,8.44 ; VOUT_1.4 13.32,9.85 ; VOUT_1.4 13.32,7.03 ; EXT_VREF.2 9.64,31.32 ; EXT_VREF.2 8.24,32.73 ; EXT_VREF.2 6.83,31.32 ; EXT_VREF.2 8.24,29.92 ; 37.78,49.67 VOUT_5.3 ; VOUT_5.3 39.18,51.08 ; VOUT_5.3 39.18,48.27 ; VOUT_5.3 40.59,49.67 ; VOUT_2.2 8.24,46 ; VOUT_2.2 9.64,44.59 ; VOUT_2.2 6.83,44.59 ; VOUT_2.2 8.24,43.19 ; 42.86,8.44 VOUT_6.4 ; VOUT_6.4 44.26,7.03 ; VOUT_6.4 45.67,8.44 ; VOUT_6.4 44.26,9.85 ; EXT_VREF.3 9.64,36.4 ; EXT_VREF.3 6.83,36.4 ; EXT_VREF.3 8.24,37.81 ; EXT_VREF.3 8.24,35 ; 11.91,36.4 EXT_VREF.4 ; EXT_VREF.4 13.32,37.81 ; EXT_VREF.4 14.72,36.4 ; EXT_VREF.4 13.32,35 ; VOUT_6.5 45.67,3.36 ; VOUT_6.5 42.86,3.36 ; VOUT_6.5 44.26,4.77 ; VOUT_6.2 39.18,4.77 ; VOUT_6.2 40.59,3.36 ; VOUT_6.2 37.78,3.36 ; 32.54,49.67 VOUT_4.4 ; VOUT_4.4 33.95,48.27 ; VOUT_4.4 35.35,49.67 ; VOUT_4.4 33.95,51.08 ; 42.86,49.67 VOUT_5.4 ; VOUT_5.4 45.67,49.67 ; VOUT_5.4 44.26,48.27 ; VOUT_5.4 44.26,51.08 ; 27.46,49.67 VOUT_4.3 ; VOUT_4.3 30.27,49.67 ; VOUT_4.3 28.87,48.27 ; VOUT_4.3 28.87,51.08 ; 32.54,44.59 VOUT_4.5 ; VOUT_4.5 35.35,44.59 ; VOUT_4.5 33.95,46 ; VOUT_4.5 33.95,43.19 ; VOUT_4.2 30.27,44.59 ; VOUT_4.2 27.46,44.59 ; VOUT_4.2 28.87,46 ; VOUT_4.2 28.87,43.19 ; 13.32,43.19 VOUT_2.5 ; VOUT_2.5 14.72,44.59 ; VOUT_2.5 11.91,44.59 ; VOUT_2.5 13.32,46 ; 3.68,58.71 EXT_VDD.2 ; EXT_VDD.2 2.49,59.9 ; EXT_VDD.2 4.87,59.9 ; EXT_VDD.2 3.68,61.09 ; VOUT_3.5 25.04,44.59 ; VOUT_3.5 23.63,46 ; VOUT_3.5 22.23,44.59 ; VOUT_3.5 23.63,43.19 ; VOUT_3.3 19.96,49.67 ; VOUT_3.3 17.15,49.67 ; VOUT_3.3 18.55,48.27 ; VOUT_3.3 18.55,51.08 ; 18.55,7.03 VOUT_0.3 ; VOUT_0.3 18.55,9.85 ; VOUT_0.3 17.15,8.44 ; VOUT_0.3 19.96,8.44 ; 28.87,7.03 VOUT_7.3 ; VOUT_7.3 28.87,9.85 ; VOUT_7.3 30.27,8.44 ; VOUT_7.3 27.46,8.44 ; VOUT_5.5 44.26,46 ; VOUT_5.5 42.86,44.59 ; VOUT_5.5 45.67,44.59 ; VOUT_5.5 44.26,43.19 ; VOUT_5.2 40.59,44.59 ; VOUT_5.2 39.18,46 ; VOUT_5.2 37.78,44.59 ; VOUT_5.2 39.18,43.19 ; EXT_VREF.5 14.72,31.32 ; EXT_VREF.5 13.32,29.92 ; EXT_VREF.5 13.32,32.73 ; EXT_VREF.5 11.91,31.32 ; 33.95,7.03 VOUT_7.4 ; VOUT_7.4 35.35,8.44 ; VOUT_7.4 32.54,8.44 ; VOUT_7.4 33.95,9.85 ; VOUT_1.2 9.64,3.36 ; VOUT_1.2 6.83,3.36 ; VOUT_1.2 8.24,4.77 ; AGND.1 22.72,59.58 ; AGND.1 21.65,58.52 ; AGND.1 22.72,57.45 ; AGND.1 23.78,58.52 ; VOUT_7.5 35.35,3.36 ; VOUT_7.5 32.54,3.36 ; VOUT_7.5 33.95,4.77 ; VOUT_0.5 25.04,3.36 ; VOUT_0.5 22.23,3.36 ; VOUT_0.5 23.63,4.77 ; VOUT_0.2 18.55,4.77 ; VOUT_0.2 19.96,3.36 ; VOUT_0.2 17.15,3.36
  vias: v1(3.18,66.67) v1(3.18,61.59) v1(3.18,56.51) v1(3.18,46.35) v1(3.18,41.27) v1(3.18,36.19) v1(5.71,59.05) v1(8.25,66.67) v1(8.25,61.59) v1(8.25,56.51) v1(8.25,46.35) v1(8.25,5.71) v1(10.79,59.05) v1(10.79,48.89) v1(10.79,38.73) v1(13.34,66.67) v1(13.34,46.35) v1(13.34,41.27) v1(13.34,10.79) v1(13.34,5.71) v1(13.85,22.45) v1(15.88,64.13) v1(15.88,59.05) v1(15.88,53.79) v1(15.88,48.89) v1(15.88,43.81) v1(15.88,8.25) v1(16.09,20.75) v1(18.09,20.9) v1(18.41,46.35) v1(18.41,41.27) v1(18.41,36.19) v1(18.41,10.79) v1(18.41,5.71) v1(20.95,48.89) v1(20.95,33.65) v1(23.49,46.35) v1(23.49,5.71) v1(26.04,48.89) v1(26.04,43.81) v1(26.04,38.73) v1(26.04,18.41) v1(27.87,30.73) v1(28.58,46.35) v1(28.58,15.87) v1(28.58,5.71) v1(29.8,29.05) v1(29.93,22.22) v1(31.12,48.89) v1(31.2,25.32) v1(31.43,27.86) v1(33,25.72) v1(33.66,46.35) v1(33.66,41.27) v1(33.66,10.79) v1(33.66,5.71) v1(33.74,27.43) v1(34.53,26.51) v1(36.2,8.25) v1(36.76,20.8) v1(36.74,16.66) v1(38.73,46.35) v1(38.73,41.27) v1(38.73,10.79) v1(38.73,5.71) v1(41.27,48.89) v1(43.82,46.35) v1(43.82,5.71)
DGND: length 87.7
  TOP w0.254: R21.1 v1(40.33,18.38) ; R16.1 v1(40.33,21.98)
  TOP w0.35: P3.5 51.44,13.35 ; P3.5 49.18,13.35 ; P3.5 50.31,12.23 ; P3.5 50.31,14.48 ; 40.16,59.74 U2.4 41.56,60.34 ; PMOD.10 44.73,23.83 ; PMOD.10 45.86,22.71 ; PMOD.10 44.73,21.58 ; PMOD.10 43.61,22.71 ; 40.8,65.02 R12.2 ; R12.2 40.8,66.52 ; R12.2 41.41,65.77 ; 50.38,53.5 P4.7 ; P4.7 50.38,55.76 ; P4.7 49.25,54.63 ; P4.7 51.5,54.63 ; 41.07,22.71 PMOD.9 ; PMOD.9 42.19,21.58 ; PMOD.9 43.32,22.71 ; 30.09,57.45 DGND.1 ; DGND.1 31.15,58.52 ; DGND.1 30.09,59.58 ; 27.25,59.47 R3.1 27.25,57.57 ; 39.11,53.45 RSTSEL.3 ; RSTSEL.3 39.11,55.71 ; RSTSEL.3 40.23,54.58 ; RSTSEL.3 37.98,54.58
  TOP w0.508: U2.7 45.43,63.07 C1.1 v1(47.9,63.07) ; v1(38.09,59.48) R8.2 38.15,60.34 U2.4 ; R10.2 v1(38.09,65.02) ; R3.1 DGND.1 ; R12.2 v1(40,65.77) ; C2.2 v1(4.94,40.66)
  L2_GND w0.35: PMOD.10 45.86,22.71 ; PMOD.10 44.73,21.58 ; PMOD.10 44.73,23.83 ; PMOD.10 43.61,22.71 ; 50.38,53.5 P4.7 ; P4.7 51.5,54.63 ; P4.7 49.25,54.63 ; P4.7 50.38,55.76 ; RSTSEL.3 40.23,54.58 ; RSTSEL.3 39.11,53.45 ; RSTSEL.3 37.98,54.58 ; RSTSEL.3 39.11,55.71 ; 42.19,21.58 PMOD.9 ; PMOD.9 43.32,22.71 ; PMOD.9 41.07,22.71 ; PMOD.9 42.19,23.83 ; 30.09,57.45 DGND.1 ; DGND.1 30.09,59.58 ; DGND.1 31.15,58.52 ; DGND.1 29.03,58.52
  BOTTOM w0.35: P3.5 50.31,14.48 ; P3.5 50.31,12.23 ; P3.5 51.44,13.35 ; 41.07,22.71 PMOD.9 ; PMOD.9 42.19,21.58 ; PMOD.9 43.32,22.71 ; DGND.1 30.09,59.58 ; DGND.1 30.09,57.45 ; DGND.1 31.15,58.52 ; DGND.1 29.03,58.52 ; P4.7 50.38,55.76 ; P4.7 50.38,53.5 ; P4.7 49.25,54.63 ; P4.7 51.5,54.63 ; 37.98,54.58 RSTSEL.3 ; RSTSEL.3 39.11,55.71 ; RSTSEL.3 40.23,54.58 ; 43.61,22.71 PMOD.10 ; PMOD.10 44.73,21.58 ; PMOD.10 45.86,22.71
  vias: v1(3.18,28.58) v1(3.18,23.5) v1(3.18,18.42) v1(3.18,13.34) v1(3.18,8.26) v1(3.18,3.18) v1(5.71,41.28) v1(5.71,36.2) v1(5.71,31.12) v1(5.71,26.04) v1(5.71,20.96) v1(5.71,15.88) v1(5.71,10.8) v1(5.71,5.72) v1(10.55,1.59) v1(15.93,1.49) v1(21.14,1.62) v1(26.35,1.62) v1(31.93,1.59) v1(36.58,1.59) v1(38.73,59.05) v1(38.73,36.19) v1(39.96,14.07) v1(41.27,66.68) v1(41.27,38.73) v1(41.66,1.7) v1(42.12,34.21) v1(42.93,31.57) v1(43.39,38.93) v1(43.49,27.1) v1(43.82,18.42) v1(46.36,66.68) v1(46.36,56.52) v1(46.36,31.12) v1(46.36,20.96) v1(46.36,15.88) v1(47.38,1.64) v1(48.9,64.14) v1(48.9,59.05) v1(48.9,53.98) v1(48.9,48.9) v1(48.9,38.73) v1(51.44,36.2) v1(51.44,31.12) v1(51.44,26.04) v1(51.44,20.96) v1(51.44,15.88) v1(51.44,5.72)
VDD_EXT: length 11
  TOP w0.635: VDD_SEL.3 C11.1 C13.1 4.83,63.75 EXT_VDD.1
ARD_SCL: length 11.3
  TOP w0.203: R6.1 42.27,59.22 42.27,60.32 43.36,61.41 45.04,61.41 U2.6 45.45,61.41 49.54,61.41 P4.10
ARD_SCLK: length 38.3
  TOP w0.203: R14.1 39.52,25.28 v1(39.5,25.29)
  BOTTOM w0.203: P4.6 48.27,49.98 48.27,25.57 46.69,24 40.8,24 v1(39.5,25.29)
ARD_SDA: length 9.9
  TOP w0.203: R23.1 43.14,59.22 43.14,60.02 43.66,60.55 45.04,60.55 U2.5 45.45,60.55 49.54,60.55 P4.9
ARD_SDI: length 40.2
  TOP w0.203: P4.4 48.83,45.46 48.83,44.06 46.44,41.67 46.44,39.67 45.9,39.14 44.48,39.14 42.37,37.03 42.37,34.87 43.52,33.72 43.52,31.54 PMOD.4
  TOP w0.254: R19.1 v1(40.33,17.18)
  BOTTOM w0.203: PMOD.4 44.59,30.33 43.21,28.95 41.36,28.95 38.56,26.16 38.56,18.94 v1(40.33,17.18)
ARD_SDO: length 7.4
  TOP w0.203: R22.1 47.07,53.06 47.07,50.36 47.89,49.55 P4.5
ARD_SYNCB: length 31.7
  TOP w0.203: R33.1 R34.1 ; R34.1 R32.1 ; R34.1 PMOD.2
  TOP w0.254: R5.1 v1(41.5,53.02)
  BOTTOM w0.203: PMOD.2 44.73,34.36 37.14,41.95 37.14,50.9 38.46,52.22 40.7,52.22 v1(41.5,53.02)
DAC_GAIN: length 32
  TOP w0.203: U1.8 v1(27.88,24.92)
  BOTTOM w0.203: v1(27.88,24.92) 27.88,23.33 35.19,16.02 45.1,16.02 P3.6 P3.4 P3.2
DAC_LDACB: length 39.1
  TOP w0.203: P5.5 49.18,26.51 41.46,26.51 40.62,27.35 40.62,31.29 PMOD.1 41.37,33.69 38.55,33.69 38.02,34.22 R36.2 LDACB.1 33.56,33.01 33.56,31.41 29.7,27.55 26.98,27.55 26.58,27.96 U1.15
DAC_OUT0: length 20
  TOP w0.33: VOUT_0.1 C15.1 R24.1 21.09,13.94 VOUT0.1 23.2,18.85 23.2,21.71 23.98,22.49 U1.2
DAC_OUT1: length 26.3
  TOP w0.33: VOUT_1.1 C16.1 R25.1 16.58,12.73 VOUT1.1 22.54,18.68 22.54,21.99 23.33,22.78 U1.1
DAC_OUT2: length 26.3
  TOP w0.33: U1.20 23.33,30.25 22.89,30.69 22.89,30.7 22.64,30.96 22.64,34.25 VOUT2.1 17.99,38.89 12.19,38.89 R26.1 C17.1 VOUT_2.1
DAC_OUT3: length 20
  TOP w0.33: VOUT_3.1 C18.1 R27.1 21.09,39.1 VOUT3.1 23.3,34.29 23.3,31.22 23.98,30.54 U1.19
DAC_OUT4: length 19.4
  TOP w0.33: U1.12 28.52,34.96 VOUT4.1 31.41,39.1 R28.1 C19.1 VOUT_4.1
DAC_OUT5: length 26.3
  TOP w0.33: U1.11 29.17,33.56 VOUT5.1 35.92,40.3 R29.1 C20.1 VOUT_5.1
DAC_OUT6: length 26.3
  TOP w0.33: U1.10 29.17,19.47 VOUT6.1 35.92,12.73 R30.1 C21.1 VOUT_6.1
DAC_OUT7: length 19.4
  TOP w0.33: VOUT_7.1 C22.1 R31.1 31.41,13.94 VOUT7.1 28.52,18.07 U1.9
DAC_RESETB: length 36.7
  TOP w0.203: P5.8 49.28,35.33 48.83,34.87 48.83,30.88 47.02,29.08 43.44,29.08 PMOD.3 ; U1.17 25.27,28.04 26.6,26.71 33.87,26.71 RESETB.1 R4.2
  BOTTOM w0.203: PMOD.3 39.28,30.33 37.12,28.17 RESETB.1
DAC_RSTSEL: length 33.1
  TOP w0.203: U1.14 v1(27.23,28.12)
  BOTTOM w0.203: RSTSEL.2 35.92,53.94 35.92,42.33 32.72,39.13 32.72,31.16 29.68,28.12 v1(27.23,28.12)
DAC_SCLK/A0: length 19.6
  TOP w0.203: 38.02,22.58 36.34,22.58 SCLK/A0.1 35.32,22.58 32,25.9 27.48,25.9 26.58,25 U1.6 ; 38.02,22.58 R16.2 R15.2 ; 38.02,22.58 R35.2 R14.2
DAC_SDI/A1: length 19.1
  TOP w0.203: R21.2 37.9,18.26 SDI/A1.1 33.56,20.02 33.56,22.1 30.16,25.5 27.66,25.5 27.23,25.06 U1.7 ; R21.2 R19.2 ; R21.2 R20.2
DAC_SDO/SDA: length 48.5
  TOP w0.203: R23.2 v1(43.9,56.14) R17.2 R18.2 R22.2 ; SDO/SDA.1 35.32,30.45 31.99,27.13 26.82,27.13 25.92,28.03 U1.16
  BOTTOM w0.203: v1(43.9,56.14) 43.53,56.14 40.01,52.62 38.28,52.62 36.74,51.07 36.74,41.98 33.53,38.78 33.53,33.26 SDO/SDA.1
DAC_SYNCB/SCL: length 51.4
  TOP w0.203: R6.2 v1(41.5,56.14) R5.2 R13.2 ; SYNCB/SCL.1 33.88,26.31 27.3,26.31 25.92,24.93 U1.5
  BOTTOM w0.203: v1(41.5,56.14) 41.5,54.7 39.83,53.03 38.08,53.03 36.33,51.28 36.33,42.16 33.13,38.96 33.13,27.06 SYNCB/SCL.1
DAC_VDD: length 14.2
  TOP w0.635: U4.2 18.03,18.68 C10.1
  L3_PWR w0.35: 18.25,23.28 VDD_VIO.1 ; VDD_VIO.1 20.51,23.28 ; VDD_VIO.1 19.38,22.15 ; 14.22,60.08 VDD_SEL.2 ; VDD_SEL.2 14.22,62.33 ; VDD_SEL.2 15.34,61.21 ; VDD_SEL.2 13.09,61.21 ; VDD.1 15.84,25.61 ; VDD.1 16.9,24.55 ; VDD.1 14.78,24.55 ; VDD.1 15.84,23.48
  vias: v1(19.04,18.98) v1(19.04,18.25) v1(24.6,19.63) v1(25.32,19.63)
DAC_VLOGIC: length 60.7
  TOP w0.254: R20.1 v1(40.33,19.58) ; R15.1 v1(40.33,20.78)
  TOP w0.33: VDD_VIO.2 C23.2 23.92,25.82 25.27,24.46 U1.4
  TOP w0.508: 44.89,64.15 U2.8 45.43,63.97 C1.2 v1(47.86,63.97) ; 44.89,64.15 44.6,64.44 R11.1 ; 44.89,64.15 v1(43.65,64.15) ; R7.1 v1(36.89,59.48) ; R9.1 v1(36.89,65.02) ; R4.1 v1(39.52,29.08) ; R1.2 VLOGIC.1 ; R36.1 v1(40.33,34.77) ; R32.2 v1(46.84,36.42)
  L3_PWR w0.35: 43.61,20.17 PMOD.12 ; PMOD.12 44.73,21.29 ; PMOD.12 44.73,19.04 ; PMOD.12 45.86,20.17 ; VDD_VIO.2 19.38,26.94 ; VDD_VIO.2 18.25,25.82 ; VDD_VIO.2 20.51,25.82 ; VLOGIC.1 31.15,54.58 ; VLOGIC.1 29.03,54.58 ; VLOGIC.1 30.09,53.52 ; VLOGIC.1 30.09,55.64 ; P3.3 50.31,11.94 ; P3.3 50.31,9.69 ; P3.3 51.44,10.81 ; P3.3 49.18,10.81 ; RSTSEL.1 35.15,54.58 ; RSTSEL.1 34.03,53.45 ; RSTSEL.1 32.9,54.58 ; RSTSEL.1 34.03,55.71 ; PMOD.11 43.32,20.17 ; PMOD.11 42.19,21.29 ; PMOD.11 41.07,20.17 ; PMOD.11 42.19,19.04
  L3_PWR w0.508: v1(36.89,59.48) 36.89,62.25 ; 36.89,62.25 41.74,62.25 v1(43.65,64.15) ; 36.89,62.25 v1(36.89,65.02)
DAC_VREF: length 23
  TOP w0.635: REF_SEL.2 VREF.1
  TOP w0.75: v1(24.96,33.5) C7.1
  L3_PWR w0.75: VREF.1 12.09,26.71 15.09,29.71 21.67,29.71 24.96,33 v1(24.96,33.5)
GAIN_IO: length 15.4
  BOTTOM w0.203: P3.1 49.05,9.53 49.05,21.3 P5.3
LDO_3V3: length 6
  TOP w0.35: 12.2,55.41 C12.1 ; C12.1 12.88,56.16 ; C12.1 12.2,56.9 ; 12.67,55.18 U3.5 13.73,54.63 ; 14.22,57.54 VDD_SEL.1 13.09,58.67
PMOD_SCLK/SDA: length 37.8
  TOP w0.203: R35.1 40.34,24 43.48,24 PMOD.8
  TOP w0.254: R18.1 v1(45.1,53.02)
  BOTTOM w0.203: PMOD.8 45.8,26.31 46.51,26.31 47.84,27.63 47.84,48.94 44.71,52.06 44.71,52.63 v1(45.1,53.02)
PMOD_SDO/SCL: length 33.1
  TOP w0.254: R13.1 v1(42.7,53.02) ; R17.1 v1(43.9,53.02)
  BOTTOM w0.203: v1(42.7,53.02) v1(43.9,53.02) 44.3,52.62 44.3,51.88 47.43,48.76 47.43,27.81 46.34,26.71 45.81,26.71 PMOD.6
UNNAMED_3_CAP_I60_N1: length 5.6
  TOP w0.572: E1.1 4.99,42.99 C2.1 P2.5
UNNAMED_3_CN8PA_I4_N2: length 25.9
  TOP w0.508: R1.1 v1(25.51,54.58)
  BOTTOM w0.635: v1(25.51,54.58) 7.27,54.58 3.26,50.57 P2.2
UNNAMED_3_CN10P_I1_N2: length 9.4
  TOP w0.203: P4.2 48.93,41.93 48.04,41.04 48.04,38.91 46.67,37.53 45.42,37.53 44.73,36.85 R34.2
UNNAMED_3_CN10P_I1_N3: length 11.6
  TOP w0.203: P4.3 47.25,41.34 47.25,39.29 46.31,38.35 45.04,38.35 43.53,36.84 R33.2
UNNAMED_3_FERRITE_I66_N2: length 4.3
  TOP w0.572: R2.1 E1.2
UNNAMED_3_IC24XX32AV2_I22_A1: length 3.3
  TOP w0.203: R9.2 R10.1 39.99,62.71 U2.2
UNNAMED_3_IC24XX32AV2_I22_A2: length 3.3
  TOP w0.203: U2.3 39.99,61.79 R8.1 R7.2
UNNAMED_3_RES_I15_N1: length 4.3
  TOP w0.203: R11.2 R12.1 42.3,65.76 42.3,64.53 41.92,64.15 U2.1
VREF_2V5: length 10.3
  TOP w0.203: 9.7,17.41 9.94,17.65 9.94,18.15 10.46,18.68 U4.6
  TOP w0.635: U4.7 C14.1 8.82,17.41 8.31,17.91 REF_SEL.3
VREF_EXT: length 7.8
  TOP w0.635: EXT_VREF.1 10.78,29.55 REF_SEL.1

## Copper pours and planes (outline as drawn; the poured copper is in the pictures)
+5V_SUP on TOP: 4.54,54 4.54,54.84 5.25,55.56 9.65,55.56 10.33,54.88 11.09,54.88 11.09,54.37 9.41,54.37 9.03,54
AGND on TOP: 6.64,3.17 46.51,3.17 46.51,13.3 39.66,13.3 37.09,15.87 37.09,35.44 41.29,39.64 45.68,39.64 45.85,39.82 45.85,51.8 27.1,51.8 26.22,52.67 26.22,67.62 0.64,67.62 0.64,33.14 3.86,33.14 3.86,42.25 6.64,42.25 ; 1 cut-out
AGND on BOTTOM, L2_GND: 6.64,3.17 46.51,3.17 46.51,13.3 39.66,13.3 37.09,15.87 37.09,35.44 41.29,39.64 45.68,39.64 45.85,39.82 45.85,51.8 27.1,51.8 26.22,52.67 26.22,67.62 0.64,67.62 0.64,33.14 3.86,33.14 3.86,42.25 6.64,42.25
DGND on TOP: 0.64,0.64 0.64,67.61 51.85,67.61 51.85,0.64 ; 2 cut-outs
DGND on BOTTOM: 0.64,0.64 0.64,67.62 51.87,67.62 51.87,0.64 ; 4 cut-outs
DGND on L2_GND: 0.64,0.64 0.64,67.62 51.87,67.62 51.87,0.64
DAC_VDD on TOP: 19.29,18 18.77,18 18.53,18.23 17.65,18.23 17.65,18.99 18.53,18.99 18.77,19.23 19.29,19.23
DAC_VDD on TOP: 24.34,19.38 24.34,19.9 24.58,20.14 24.58,22.22 24.46,22.34 24.46,24.41 24.79,24.41 24.79,22.76 25.34,22.21 25.34,20.14 25.58,19.9 25.58,19.38
DAC_VDD on L3_PWR: 26.22,0.64 26.22,24.35 17.48,24.35 17.48,67.62 0.64,67.62 0.64,0.64
DAC_VLOGIC on L3_PWR: 17.89,67.62 51.87,67.62 51.87,0.64 26.64,0.64 26.64,24.76 17.89,24.76
DAC_VREF on TOP: 24.58,32.9 24.58,30.81 24.46,30.69 24.46,28.62 24.79,28.62 24.79,30.27 25.34,30.82 25.34,32.9
LDO_3V3 on TOP: 11.91,54.37 11.91,58.87 12.52,59.49 15.04,59.49 15.04,55.19 14.23,54.37

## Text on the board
Ref Des/Silkscreen Bottom: NC | A0 | A1 | A2 | A3 | A4 | A5 | 3.3V | 5V | GND | VIN | IOREF | RESET | SECONDARY SIDE | BR-070004 REV B Z | 4 | 2 | 13 | 12 | 8 | 7 | SCL | SDA | AREF | ~5 | ~3 | ~11 | ~10 | ~9 | ~6 | RX<-0 | TX->1 | ANALOG IN | POWER | DIGITAL (PWM ~)
User.Comments: 1 | 2 | COMPONENT KEEPOUT AREA | COMPONENTS GREATER THAN 1.5MM | 1.    RoHS COMPLIANCE: ASSEMBLY VENDOR SHOULD ASSURE COMPLIANCE | > GAIN (P3): 1-2 | > P1, P2, P4, AND P5. | > VDD_SEL : POSITION A or 1-2 | > VDD_SEL: PIN1 & PIN2 | > VDD_VIO : DISCONNECTED | > REF_SEL : POSITION A or 1-2 | > RSTLSEL : POSITION A or 1-2 | 5.    DO NOT TRIM EXCESS TAIL LENGTH OF THE FOLLOWING: | 6.    INSTALL DEFAULT POSITION OF SHUNT(MFG_PN: 881545-2) ON THE FOLLOWING: | 7.    BOARDS TO BE SHIPPED SINGULATED AFTER ASSEMBLY PROCESS. | 8.    SMOOTHEN EDGES AND FREE FROM BURRS AFTER DEPANELIZATION PROCESS. | 9.    STICKER WITH MODEL NAME PRINTED SHOULD BE PROVIDED AS PER GENERIC INFORMATION TABLE AND ATTACHED TO THE SECONDARY SIDE. | WITH LEAD-FREE AND RoHS PCB ASSEMBLY STANDARDS (EU RoHS | DIRECTIVE 2002/95/EC). | BOARD NUMBER: | BR-070004 | BR-070005 | BR-070006 | BR-070007 | MODEL NAME: | EVAL-AD5676R2ARDZ | EVAL-AD5675RARDZ | EVAL-AD5676ARDZ | GENERIC INFORMATION: | PIN SHORT: | PIN1 & PIN2 | PIN2 & PIN3 | BOM: | 05-070004-01-A | 05-070004-02-A | 05-070004-03-A | 05-070004-04-A
Ref Des/Silkscreen Top: 1 | A | B | GAIN | BR-070004 REV B Z | PRIMARY SIDE | + | EVAL-
PAGE_OUTLINE: B | AS PER ECR-114919 | 11JUL23 | D.DALISAY | CUSTOMER EVALUATION Z
DIMENSION: - | " " | (REF) | DIA MAX
User.13: ROHS COMPLIANCE NOTE: | HOMOGENOUS MATERIALS IN THIS BOARD SHALL BE COMPLIANT | THE EU RoHS DIRECTIVE 2002/95/EC | 15.    BOARDS TO BE SHIPPED IN ARRAY AND KEEP INTACT. | 16.    PANEL TO BE SUBJECTED TO CUSTOMER(S) APPROVAL.
User.15: BELOW THIS LINE | EXTEND BOARD | IF REQUIRED
User.17: L2 GND | 08-      -07
User.18: L3 PWR | 08-      -08
User.36: PER ECR-094468 | B | 28MAY20 | PD
User.38: PAGE 1 OF 5 | TOP SIDE VIEW | VIEW OF SILKSCREEN, PINS, VIAS, | ETCH AND REFERENCE INFORMATION. | TEMPLATE NOTES. | 01.COMPONENTS ARE PLACED ON THIS SIDE. | 02.CONNECTORS P1,P2.P4 & P5 ARE PLACED | ON THIS SIDE OF THE BOARD. | 03.IF THE BOARD NEEDS TO BE INCREASED | IT CAN BE INCREASED IN THE DIRECTION | OF THE ARROWS. | 04.THE BOARD IS SET-UP AS A 4 LAYER | BOARD. MAKE SURE ANY SUBSEQUENT CHANGES, | MANUAL OR AUTOMATIC, DO NOT RESULT IN | ANY UNINTENDED CONSEQUENCES. | 05.THE EXISTING ROUTING CAN BE ALTERED AS | IS ROUTED TO CLOSE THE NETS ON THE | TEMPLATE BOARD.
User.39: PAGE 2 OF 5 | BOTTTOM SIDE VIEW | VIEW OF SILKSCREEN, PINS, VIAS, | ETCH AND REFERENCE INFORMATION. | TEMPLATE NOTES. | 01.COMPONENTS ARE PLACED ON THIS SIDE. | 02.CONNECTORS P3 IS PLACED ON THIS SIDE. THE | OTHER CONNECTORS ARE SOLDERED THIS SIDE. | 03.THE TEMPLATE IS VIEWED LOOKING FROM THE | TOP SIDE OF THE BOARD. THE RESULT IS | THAT TEXT IS MIRRORED. | 04.THE BOARD IS SET-UP AS A 4 LAYER | BOARD. MAKE SURE ANY SUBSEQUENT CHANGES, | MANUAL OR AUTOMATIC, DO NOT RESULT IN | ANY UNINTENDED CONSEQUENCES.
User.40: PAGE 3 OF 5 | PCB FAB SHEET 1 | NCDRILL LEGEND, APPROPRIATE | DETAILS AND OUTLINE DIMENSION NOTES. | 01. EACH TIME THE NC DRILL LEGEND | IS RUN, THE HOLE CHART MUST BE | CHECKED TO ASSURE THE TOLERANCES | & NOTES CORRESPOND TO THE RIGHT | PADSTACKS.
User.41: PAGE 4 OF 5 | PCB FAB SHEET 2 | FABRICATION NOTES. ALTER DEPENDING ON THE | REQUIREMENTS OF THE DESIGN.
User.42: TEMPLATE REVISION HISTORY | TEMPLATE BOARDS FOR EVAL PROVIDE INFORMATION IN THE | REFERENCE; ALONG WITH EMBEDDED ALLEGRO | PROPERTIES FOR PCB DESIGN USE. | THEY MAINTAIN A SEPARATE TITLE BLOCK AND PART | NUMBER FOR REVISION TRACKING, INDEPENDENT OF | THE ACTUAL MANUFACTURED DUT-SPECIFIC BOARD | DESIGN. | TEMPLATE BOARDS DISPLAY AS "FILE VIEWS", AND | DUT-SPECIFIC APPLICATION BOARDS ARE | MANUFACTURED FROM ARTWORK "FILM VIEWS"AND NC | DATA. | AND TITLE BLOCK CONTENT IS TRACKING THE | MANUFACTURED BOARD PART NUMBER AND REV, | AND NOT THE TEMPLATE BOARD PART NUMBER AND | REV. | PAGE 5 OF 5 | MAKE SURE THE DUT-SPECIFIC BOARD INFORMATION | REV.A (20APR20) | 1. INITIAL RELEASE. | REV.B (28MAY20) PER ECR-094468 | 1. BRING FILES INTO TEMPLATE FORMAT.
User.45: 1 | FABRICATION | 09-012345-01 | A | FIGURE | SIZE | 0.254 | 1.016 | 1.143 | 1.1684 | 1.27 | 1.7018 | DRILL CHART: TOP to BOTTOM | FINISHED HOLES IN MILLIMETERS | PLATED | QTY | 175 | 19 | 61 | 9 | 2 | 36 | TOLERANCE/NOTES
